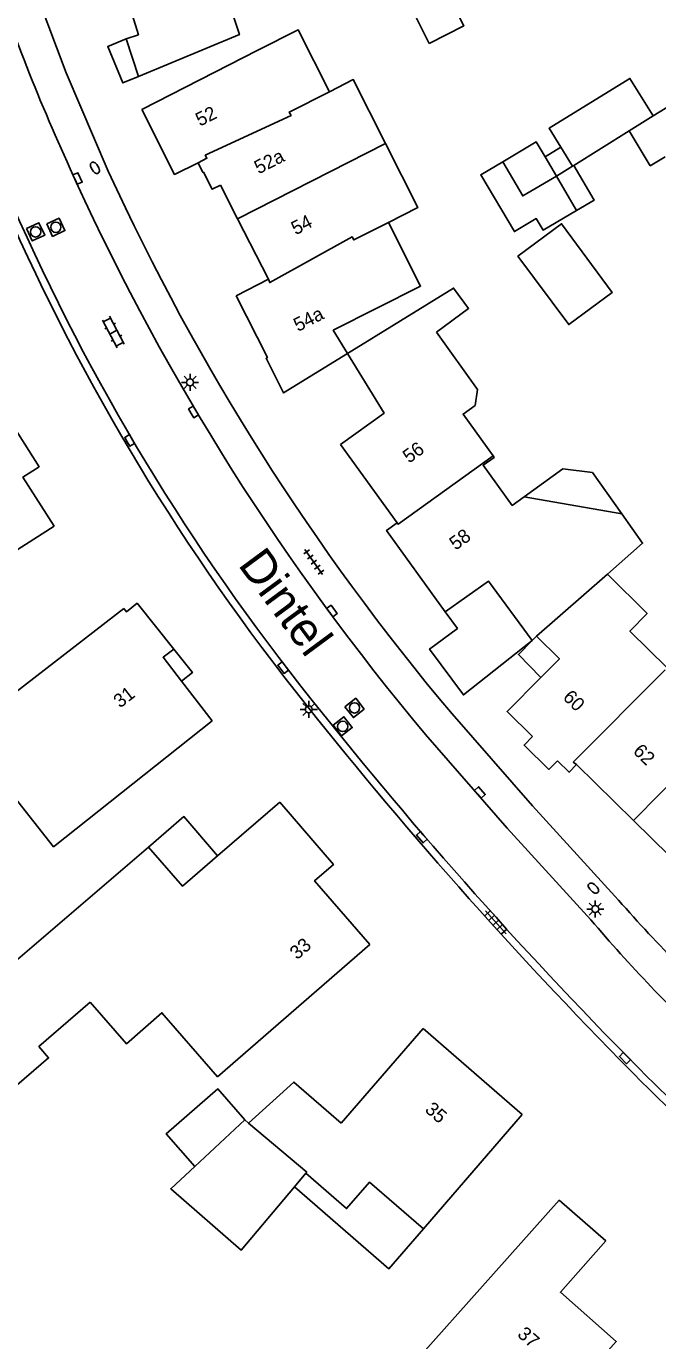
# Model space of a CAD drawing. Extents: x 126000 to 131009, y 393000 to 395500.
# Drawn here: x 130394.9 to 130441, y 394850.8 to 394946.8 of the extents above; entities that cross this region are included whole.
import ezdxf

# ---------------------------------------------------------------- set-up
doc = ezdxf.new("R2010")
doc.units = 0
for name, color, linetype in [('gg-anno-huisnummerreeks BGT', 7, 'Continuous'), ('gg-anno-openbare ruimte label', 7, 'Continuous'), ('gg-bbg-gedigitaliseerde bebouwing', 7, 'Continuous'), ('gg-bbg-gedigitaliseerde bijgebouw', 7, 'Continuous'), ('gg-bbg-hoofdgebouw', 7, 'Continuous'), ('gg-bbg-luifel en loopbrug', 7, 'Continuous'), ('gg-bbg-tussenscheiding', 7, 'Continuous'), ('gg-knt-verharding', 7, 'Continuous'), ('gt-symb-brandkraan', 7, 'Continuous'), ('gt-symb-klinker verharding', 7, 'Continuous'), ('gt-symb-kolk', 7, 'Continuous'), ('gt-symb-lichtmast', 7, 'Continuous'), ('gt-symb-rioolschacht', 7, 'Continuous'), ('gt-symb-tegel verharding', 7, 'Continuous')]:
    doc.layers.add(name, color=color, linetype=linetype)

# ---------------------------------------------------------------- blocks, each defined once
blk = doc.blocks.new('gt0-KOLK')
at = {"layer": 'gt-symb-kolk'}
blk.add_lwpolyline([(0, 0), (0.375, 0), (0.375, 0.4), (-0.375, 0.4), (-0.375, 0), (0, 0)], dxfattribs=at)
blk = doc.blocks.new('gt0-LMAST')
at = {"layer": 'gt-symb-lichtmast'}
for p, q in [((-0.182, 0.173), (-0.447, 0.438)), ((-0.005, 0.246), (-0.005, 0.621)), ((0.172, 0.173), (0.437, 0.438)), ((-0.255, -0.004), (-0.63, -0.004)), ((-0.182, -0.181), (-0.447, -0.446)), ((-0.005, -0.254), (-0.005, -0.629)), ((0.437, -0.446), (0.172, -0.181)), ((0.245, -0.004), (0.62, -0.004))]:
    blk.add_line(p, q, dxfattribs=at)
blk.add_circle((-0.005, -0.004), 0.25, dxfattribs=at)
blk = doc.blocks.new('gt0-RS')
at = {"layer": 'gt-symb-rioolschacht'}
blk.add_lwpolyline([(-0.5, -0.5), (0.5, -0.5), (0.5, 0.5), (-0.5, 0.5)], close=True, dxfattribs=at)
blk.add_circle((0, 0), 0.375, dxfattribs=at)
blk = doc.blocks.new('gt0-TEG1')
at = {"layer": 'gt-symb-tegel verharding'}
for p, q in [((-1.125, 0), (1.125, 0)), ((-0.9, -0.25), (-0.9, 0.25)), ((-0.45, -0.25), (-0.45, 0.25)), ((0, -0.25), (0, 0.25)), ((0.45, -0.25), (0.45, 0.25)), ((0.9, -0.25), (0.9, 0.25))]:
    blk.add_line(p, q, dxfattribs=at)
blk = doc.blocks.new('gt0-BR')
at = {"layer": 'gt-symb-brandkraan'}
for centre, radius, start, end in [((-0.244, 0), 0.206, 107.56694, 252.43307), ((0.599, -2.664), 3, 106.89205, 107.56694), ((0, -0.691), 0.938, 73.10799, 106.89205), ((-0.599, -2.664), 3, 72.43309, 73.10799), ((0.244, 0), 0.206, 287.56695, 72.43309), ((0.599, 2.664), 3, 252.43307, 253.10797), ((0, 0.691), 0.938, 253.10797, 286.89206), ((-0.599, 2.664), 3, 286.89206, 287.56695)]:
    blk.add_arc(centre, radius, start, end, dxfattribs=at)
blk = doc.blocks.new('gt0-KL1')
at = {"layer": 'gt-symb-klinker verharding'}
for p, q in [((-1.15, 0.3), (1.15, 0.3)), ((-1, -0.3), (-1, 0.3)), ((-0.5, 0.3), (-0.5, 0.45)), ((0, -0.3), (0, 0.3)), ((0.5, 0.3), (0.5, 0.45)), ((1, -0.3), (1, 0.3)), ((-1.15, -0.3), (1.15, -0.3)), ((-0.5, -0.45), (-0.5, -0.3)), ((0.5, -0.45), (0.5, -0.3))]:
    blk.add_line(p, q, dxfattribs=at)

msp = doc.modelspace()

# ---------------------------------------------------------------- linework, layer by layer
at = {"layer": 'gg-bbg-gedigitaliseerde bebouwing'}
for p, q in [((130440.66, 394940.3), (130449.936, 394946.025)), ((130403.295, 394940.773), (130411.78, 394945.09)), ((130431.23, 394912.47), (130438.373, 394911.227)), ((130403.792, 394886.905), (130391.976, 394876.777)), ((130408.82, 394870.12), (130419.96, 394879.783)), ((130417.857, 394866.735), (130423.854, 394873.642)), ((130423.88, 394859.02), (130431.087, 394867.374))]:
    msp.add_line(p, q, dxfattribs=at)
for points in [[(130417.003, 394942.069), (130414.726, 394946.578), (130411.78, 394945.09)], [(130421.1, 394938.287), (130418.745, 394942.949), (130417.003, 394942.069)], [(130441.534, 394937.314), (130440.45, 394936.66), (130438.91, 394939.22)], [(130421.32, 394932.521), (130423.465, 394933.605), (130421.1, 394938.287)], [(130418.334, 394922.947), (130417.293, 394924.646), (130423.67, 394927.87), (130421.32, 394932.521)], [(130418.334, 394922.947), (130426.08, 394927.725), (130427.177, 394926.245), (130424.833, 394924.507)], [(130424.833, 394924.507), (130427.83, 394920.32), (130427.66, 394919.15), (130426.78, 394918.52), (130428.971, 394915.47)], [(130428.971, 394915.47), (130429.05, 394915.36), (130428.24, 394914.78), (130430.37, 394911.85), (130431.23, 394912.47)], [(130437.33, 394906.82), (130439.897, 394909.089), (130438.373, 394911.227)], [(130437.33, 394906.82), (130440.22, 394903.95), (130438.97, 394902.68), (130441.694, 394899.994)], [(130392.513, 394892.388), (130396.851, 394886.918), (130408.44, 394896.11)], [(130399.526, 394875.584), (130395.778, 394872.331), (130396.49, 394871.5), (130390.75, 394866.58), (130385.6, 394872.6), (130391.34, 394877.51), (130391.976, 394876.777)], [(130399.526, 394875.584), (130402.17, 394872.54), (130404.77, 394874.8), (130408.82, 394870.12)], [(130417.857, 394866.735), (130414.397, 394869.737), (130411.099, 394866.744)], [(130415.282, 394863.082), (130418.26, 394860.498), (130419.939, 394862.434), (130423.88, 394859.02)], [(130433.799, 394861.113), (130417.99, 394843.39), (130421.057, 394840.687)]]:
    msp.add_lwpolyline(points, dxfattribs=at)
at = {"layer": 'gg-bbg-gedigitaliseerde bijgebouw'}
for p, q in [((130424.3, 394945.59), (130423.02, 394948.11)), ((130434.856, 394936.686), (130438.91, 394939.22)), ((130433.911, 394938.01), (130434.764, 394936.628)), ((130432.766, 394937.303), (130433.594, 394935.897)), ((130433.594, 394935.897), (130434.764, 394936.628)), ((130411.099, 394866.744), (130410.83, 394866.97)), ((130414.448, 394862.09), (130415.282, 394863.082))]:
    msp.add_line(p, q, dxfattribs=at)
for points in [[(130424.3, 394945.59), (130426.83, 394946.88), (130425.554, 394949.401)], [(130440.66, 394940.3), (130438.969, 394943.041), (130433.057, 394939.392), (130433.911, 394938.01)], [(130429.67, 394936.95), (130432.12, 394938.4), (130432.766, 394937.303)], [(130435.07, 394933.39), (130432.62, 394931.96), (130432.121, 394932.802), (130430.521, 394931.855), (130428.067, 394936.001), (130429.67, 394936.95)], [(130435.07, 394933.39), (130436.352, 394934.145), (130434.856, 394936.686)], [(130430.782, 394930.059), (130434.491, 394925.054), (130437.676, 394927.414), (130433.967, 394932.419), (130430.782, 394930.059)], [(130410.83, 394866.97), (130408.864, 394869.236), (130405.087, 394865.96), (130407.167, 394863.562)], [(130407.167, 394863.562), (130405.416, 394861.944), (130410.559, 394857.461), (130414.448, 394862.09)]]:
    msp.add_lwpolyline(points, dxfattribs=at)
at = {"layer": 'gg-bbg-hoofdgebouw'}
for p, q in [((130403.063, 394943.186), (130402.157, 394945.922)), ((130409.05, 394935.245), (130410.302, 394932.786)), ((130410.302, 394932.786), (130412.551, 394928.365)), ((130412.551, 394928.365), (130410.189, 394927.161)), ((130421.967, 394910.586), (130417.826, 394916.297)), ((130396.897, 394910.334), (130392.008, 394907.214)), ((130432.142, 394902.309), (130431.83, 394901.994)), ((130408.44, 394896.11), (130406.205, 394899.009)), ((130439.219, 394888.839), (130435.067, 394892.921)), ((130413.383, 394890.181), (130408.838, 394886.263)), ((130443.379, 394884.75), (130439.219, 394888.839)), ((130431.087, 394867.374), (130423.854, 394873.642))]:
    msp.add_line(p, q, dxfattribs=at)
for points in [[(130411.713, 394955.349), (130411.758, 394955.035), (130411.677, 394955.019), (130412.57, 394949.322), (130410.6, 394948.716), (130410.619, 394948.654), (130409.724, 394948.365), (130410.436, 394946.239), (130403.063, 394943.186)], [(130402.157, 394945.922), (130403.056, 394946.227), (130401.273, 394951.933)], [(130403.295, 394940.773), (130405.692, 394936.028), (130407.407, 394936.881)], [(130407.407, 394936.881), (130407.758, 394936.167), (130407.81, 394936.19), (130408.45, 394934.94), (130409.05, 394935.245)], [(130418.334, 394922.947), (130413.662, 394920.064), (130412.378, 394922.598), (130412.476, 394922.647), (130410.189, 394927.161)], [(130417.826, 394916.297), (130420.999, 394918.599), (130418.334, 394922.947)], [(130396.897, 394910.334), (130394.605, 394913.917), (130395.793, 394914.68), (130391.997, 394920.631)], [(130425.476, 394904.068), (130421.187, 394910.024), (130421.967, 394910.586)], [(130431.83, 394901.994), (130428.622, 394906.323), (130425.476, 394904.068)], [(130401.982, 394904.32), (130391.832, 394896.474), (130392.016, 394896.236)], [(130405.638, 394901.349), (130402.954, 394904.706), (130402.172, 394904.081), (130401.982, 394904.32)], [(130432.452, 394899.282), (130433.813, 394900.655), (130432.142, 394902.309)], [(130406.205, 394899.009), (130404.856, 394900.759), (130405.638, 394901.349)], [(130431.85, 394894.981), (130429.994, 394896.804), (130432.452, 394899.282)], [(130433.663, 394893.2), (130433.047, 394892.572), (130431.229, 394894.348), (130431.85, 394894.981)], [(130435.067, 394892.921), (130434.517, 394892.361), (130433.663, 394893.2)], [(130419.96, 394879.783), (130415.929, 394884.446), (130417.295, 394885.617), (130413.383, 394890.181)], [(130408.838, 394886.263), (130406.265, 394884.045), (130403.792, 394886.905)], [(130430.417, 394842.294), (130437.961, 394850.784), (130433.886, 394854.391), (130437.196, 394858.135), (130433.799, 394861.113)]]:
    msp.add_lwpolyline(points, dxfattribs=at)
at = {"layer": 'gg-bbg-luifel en loopbrug'}
msp.add_line((130433.911, 394938.01), (130432.766, 394937.303), dxfattribs=at)
for points in [[(130403.063, 394943.186), (130401.909, 394942.708), (130400.809, 394945.364), (130402.157, 394945.922)], [(130438.373, 394911.227), (130436.221, 394914.247), (130434.074, 394914.514), (130431.23, 394912.47)], [(130431.83, 394901.994), (130426.804, 394898.008), (130424.324, 394901.354), (130426.366, 394902.867), (130425.476, 394904.068)], [(130431.83, 394901.994), (130430.813, 394900.954), (130432.452, 394899.282)], [(130405.638, 394901.349), (130407, 394899.645), (130406.205, 394899.009)], [(130408.838, 394886.263), (130406.37, 394889.127), (130403.792, 394886.905)], [(130423.88, 394859.02), (130421.355, 394856.106), (130414.448, 394862.09)]]:
    msp.add_lwpolyline(points, dxfattribs=at)
at = {"layer": 'gg-bbg-tussenscheiding'}
for p, q in [((130440.66, 394940.3), (130438.91, 394939.22)), ((130410.302, 394932.786), (130421.1, 394938.287)), ((130434.764, 394936.628), (130434.856, 394936.686)), ((130433.594, 394935.897), (130435.07, 394933.39)), ((130432.142, 394902.309), (130437.33, 394906.82)), ((130439.219, 394888.839), (130445.89, 394895.6)), ((130410.83, 394866.97), (130407.167, 394863.562))]:
    msp.add_line(p, q, dxfattribs=at)
for points in [[(130417.003, 394942.069), (130414.07, 394940.58), (130414.2, 394940.34), (130407.93, 394937.43), (130408.054, 394937.203), (130407.407, 394936.881)], [(130429.67, 394936.95), (130431.14, 394934.46), (130433.594, 394935.897)], [(130421.32, 394932.521), (130418.78, 394931.24), (130418.67, 394931.46), (130412.65, 394928.13), (130412.551, 394928.365)], [(130421.967, 394910.586), (130422.03, 394910.48), (130428.971, 394915.47)], [(130441.553, 394899.853), (130434.83, 394893.11), (130435.067, 394892.921)], [(130415.282, 394863.082), (130415.353, 394863.167), (130411.099, 394866.744)]]:
    msp.add_lwpolyline(points, dxfattribs=at)
at = {"layer": 'gg-knt-verharding'}
for points in [[(130400.844, 394936.262), (130397.779, 394943.457), (130395.019, 394950.775), (130395.417, 394950.912), (130392.754, 394959.414), (130391.222, 394965.211), (130390.069, 394970.041)], [(130437.873, 394883.326), (130431.836, 394889.904), (130425.966, 394896.63)], [(130436.113, 394881.592), (130429.995, 394888.29), (130424.036, 394895.124)]]:
    msp.add_lwpolyline(points, dxfattribs=at)
for centre, radius, start, end in [((130537.726, 395000.202), 153.532, 198.50282, 204.93954), ((130559.482, 395009.041), 174.536, 204.64458, 220.09515), ((130560.031, 395009.426), 177.65, 204.60368, 220.04653), ((130541.704, 394998.601), 161.985, 203.65268, 218.72128), ((130541.763, 394998.636), 161.503, 203.65561, 218.71891), ((130671.88, 395101.047), 327.636, 218.45873, 224.92803), ((130672.133, 395101.263), 327.418, 218.46084, 224.92354), ((130525.407, 394959.53), 116.057, 221.04161, 227.48656), ((130519.69, 394952.399), 109.539, 220.27157, 227.15169), ((130515.483, 394945.615), 107.139, 225.14508, 232.30997), ((130514.261, 394944.518), 104.95, 225.19683, 232.54749)]:
    msp.add_arc(centre, radius, start, end, dxfattribs=at)

# ---------------------------------------------------------------- block references
at = {"layer": 'gt-symb-brandkraan'}
for p, rotation in [((130399.875, 394936.508), -58.40750843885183), ((130436.302, 394883.9), -44.51376743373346)]:
    msp.add_blockref('gt0-BR', p, dxfattribs=dict(at, rotation=rotation))
at = {"layer": 'gt-symb-klinker verharding', "rotation": -62.10272897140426}
msp.add_blockref('gt0-KL1', (130401.218, 394924.508), dxfattribs=at)
at = {"layer": 'gt-symb-kolk'}
for p, rotation in [((130398.423, 394935.644), -65.22886109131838), ((130406.905, 394918.576), -59.537359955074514), ((130402.239, 394916.501), -59.252527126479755), ((130417.029, 394904.025), -53.416578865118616), ((130413.464, 394899.884), -52.5571636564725), ((130427.844, 394890.756), -49.29925519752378), ((130423.909, 394887.75), 130.78156719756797), ((130438.745, 394871.626), 134.67584063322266)]:
    msp.add_blockref('gt0-KOLK', p, dxfattribs=dict(at, rotation=rotation))
at = {"layer": 'gt-symb-lichtmast'}
for p in [(130406.83, 394920.845), (130415.507, 394896.959), (130436.438, 394882.377)]:
    msp.add_blockref('gt0-LMAST', p, dxfattribs=at)
at = {"layer": 'gt-symb-rioolschacht'}
for p, rotation in [((130397.015, 394932.165), -65.04884837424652), ((130395.538, 394931.83), -65.04884837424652), ((130418.841, 394897.062), -51.9039146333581), ((130417.976, 394895.715), -51.9039146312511)]:
    msp.add_blockref('gt0-RS', p, dxfattribs=dict(at, rotation=rotation))
at = {"layer": 'gt-symb-tegel verharding'}
for p, rotation in [((130415.866, 394907.716), -54.89531311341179), ((130429.17, 394881.401), -47.55289814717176)]:
    msp.add_blockref('gt0-TEG1', p, dxfattribs=dict(at, rotation=rotation))

# ---------------------------------------------------------------- texts
at = {"layer": 'gg-anno-huisnummerreeks BGT'}
for s, rotation, p in [('52', 26.8, (130407.545, 394939.509)), ('52a', 27, (130411.835, 394936.024)), ('54', 26.9, (130414.534, 394931.574)), ('54a', 26.9, (130414.708, 394924.514)), ('56', 35.9, (130422.824, 394914.893)), ('58', 35.8, (130426.229, 394908.538)), ('31', 37.6, (130401.711, 394897.014)), ('60', 315.5, (130434.006, 394897.769)), ('62', 315.5, (130439.131, 394893.833)), ('33', 40.8, (130414.645, 394878.627)), ('35', 319.1, (130423.923, 394867.628)), ('37', 318.5, (130430.676, 394851.223))]:
    msp.add_text(s, height=1, rotation=rotation, dxfattribs=at).set_placement(p)
at = {"layer": 'gg-anno-openbare ruimte label'}
msp.add_text('Dintel', height=2.5, rotation=306.4, dxfattribs=at).set_placement((130410.277, 394907.515))

doc.saveas('drawing.dxf')
